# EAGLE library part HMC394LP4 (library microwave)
GaAs HBT PROGRAMMABLE 5-BIT COUNTER, DC - 2.2 GHz Source: http://www.hittite.com/product_info/product_specs/dividersdetectors/hmc394lp4.pdf
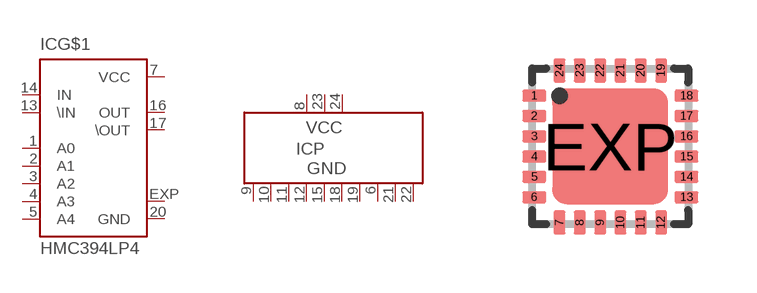
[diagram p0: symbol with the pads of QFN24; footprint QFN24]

Designator prefix IC; gates G$1=HMC394LP4 P=P3VCC10GND

## HMC394LP4  [QFN24]
1  G$1:A0  in
2  G$1:A1  in
3  G$1:A2  in
4  G$1:A3  in
5  G$1:A4  in
6  P:GND  pwr
7  G$1:VCC  pwr
8  P:VCC  pwr
9  P:GND  pwr
10  P:GND  pwr
11  P:GND  pwr
12  P:GND  pwr
13  G$1:\IN  in
14  G$1:IN  in
15  P:GND  pwr
16  G$1:OUT  out
17  G$1:\OUT  out
18  P:GND  pwr
19  P:GND  pwr
20  G$1:GND  pwr
21  P:GND  pwr
22  P:GND  pwr
23  P:VCC  pwr
24  P:VCC  pwr
EXP  G$1:EXP  pas

## Footprint QFN24 (pad centres in mm)
QFN 4x4 mm Source: http://www.hittite.com/product_info/product_specs/dividersdetectors/hmc394lp4.pdf
smd 0.6 x 0.3: 1 -1.905,1.27; 2 -1.905,0.762; 3 -1.905,0.254; 4 -1.905,-0.254; 5 -1.905,-0.762; 6 -1.905,-1.27; 13 1.905,-1.27; 14 1.905,-0.762; 15 1.905,-0.254; 16 1.905,0.254; 17 1.905,0.762; 18 1.905,1.27
smd 0.3 x 0.6: 7 -1.27,-1.905; 8 -0.762,-1.905; 9 -0.254,-1.905; 10 0.254,-1.905; 11 0.762,-1.905; 12 1.27,-1.905; 19 1.27,1.905; 20 0.762,1.905; 21 0.254,1.905; 22 -0.254,1.905; 23 -0.762,1.905; 24 -1.27,1.905
smd 2.9 x 2.9: EXP 0,0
